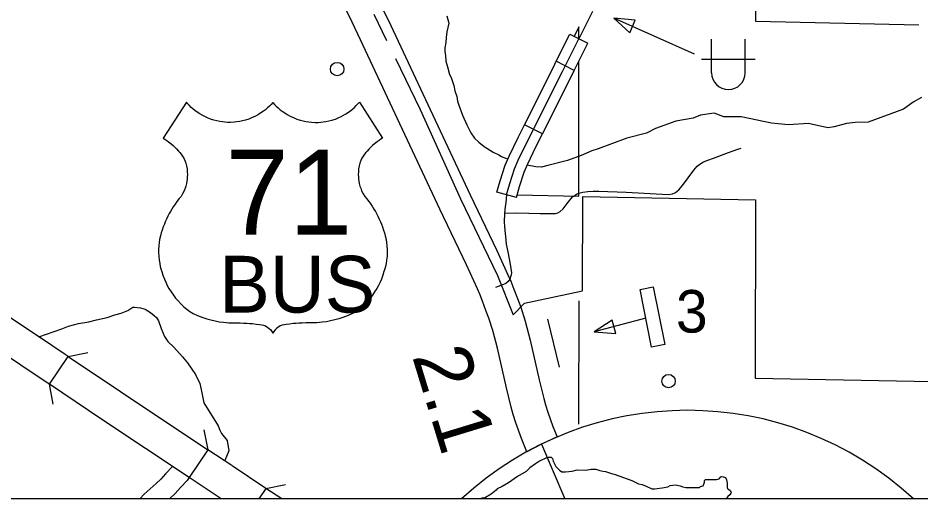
# Model space of a CAD drawing. Extents: x 1382482 to 1385815, y 1168351 to 1170484.
# Drawn here: x 1384529.1 to 1384797.7, y 1168702.4 to 1168845.5 of the extents above; entities that cross this region are included whole.
import ezdxf

# ---------------------------------------------------------------- set-up
doc = ezdxf.new("R2010")
doc.units = 0
for name, color, linetype in [('15', 7, 'Continuous'), ('22', 7, 'Continuous'), ('32', 7, 'Continuous'), ('35', 7, 'Continuous'), ('37', 7, 'Continuous'), ('46', 7, 'Continuous'), ('48', 7, 'Continuous'), ('5', 7, 'Continuous'), ('57', 7, 'Continuous'), ('6', 7, 'Continuous'), ('Default', 7, 'Continuous'), ('R_No Plot', 7, 'Continuous')]:
    doc.layers.add(name, color=color, linetype=linetype)

msp = doc.modelspace()

# ---------------------------------------------------------------- linework, layer by layer
at = {"layer": '15'}
msp.add_line((1384602.84, 1168705.52), (1384592.76, 1168712.26), dxfattribs=at)
for points in [[(1384689.48, 1168720.81), (1384684.86, 1168718.69), (1384680.47, 1168716.41), (1384678.87, 1168720.37), (1384677.21, 1168725.04), (1384676.41, 1168727.54), (1384675.81, 1168729.71), (1384674.38, 1168735.47), (1384671.72, 1168747.23), (1384670.33, 1168752.47), (1384669.17, 1168756.22), (1384668.32, 1168758.5), (1384667.27, 1168761.27), (1384666.5, 1168763.34), (1384665.77, 1168764.88), (1384662.49, 1168772.09), (1384654.58, 1168788.57), (1384641.95, 1168815.49), (1384630.97, 1168839), (1384628.47, 1168844.22), (1384622.3, 1168856.93)], [(1384637.48, 1168848.56), (1384640.01, 1168843.27), (1384651.01, 1168819.73), (1384663.61, 1168792.85), (1384671.55, 1168776.33), (1384674.84, 1168769.09), (1384675.73, 1168767.22), (1384676.63, 1168764.78), (1384677.67, 1168762.03), (1384678.64, 1168759.45), (1384679.94, 1168755.23), (1384681.43, 1168749.62), (1384684.11, 1168737.78), (1384685.48, 1168732.26), (1384686, 1168730.41), (1384686.69, 1168728.23), (1384688.22, 1168723.92), (1384689.48, 1168720.81)], [(1384535.46, 1168750.55), (1384528.18, 1168755.37), (1384526.88, 1168756.23)], [(1384544.01, 1168744.78), (1384542.81, 1168745.59), (1384535.49, 1168750.52)], [(1384529.93, 1168742.21), (1384522.3, 1168747.27), (1384521.35, 1168747.9)], [(1384585.54, 1168717.02), (1384579.98, 1168708.71), (1384553.99, 1168725.99), (1384538.42, 1168736.49), (1384544.01, 1168744.78)], [(1384544.01, 1168744.78), (1384559.55, 1168734.3), (1384585.54, 1168717.02)], [(1384538.42, 1168736.49), (1384537.47, 1168737.13), (1384529.9, 1168742.23)], [(1384684.86, 1168718.69), (1384691.81, 1168702.36)], [(1384592.72, 1168712.29), (1384585.54, 1168717.02)], [(1384589.57, 1168702.36), (1384587.2, 1168703.95), (1384579.98, 1168708.71)], [(1384607.54, 1168702.36), (1384602.84, 1168705.52), (1384600.73, 1168702.36)]]:
    msp.add_lwpolyline(points, dxfattribs=at)
at = {"layer": '22'}
for points in [[(1384604.91, 1168820.38), (1384604.39, 1168819.79), (1384603.89, 1168819.27), (1384603.31, 1168818.74), (1384602.7, 1168818.21), (1384602.1, 1168817.74), (1384601.38, 1168817.24), (1384600.6, 1168816.75), (1384599.72, 1168816.27), (1384598.6, 1168815.75), (1384597.74, 1168815.42), (1384596.77, 1168815.1), (1384595.88, 1168814.87), (1384595.06, 1168814.7), (1384594.2, 1168814.57), (1384593.4, 1168814.49), (1384592.31, 1168814.44), (1384591.43, 1168814.45), (1384590.66, 1168814.49), (1384589.92, 1168814.57), (1384589.18, 1168814.68), (1384588.25, 1168814.87), (1384587.38, 1168815.1), (1384586.33, 1168815.44), (1384585.44, 1168815.79), (1384584.63, 1168816.16), (1384583.89, 1168816.55), (1384583.2, 1168816.95), (1384582.44, 1168817.46), (1384581.74, 1168817.97), (1384581.13, 1168818.47), (1384580.62, 1168818.92), (1384580.1, 1168819.42), (1384579.59, 1168819.96), (1384579.18, 1168820.44), (1384572.25, 1168809.73), (1384572.75, 1168809.43), (1384573.34, 1168809.05), (1384573.89, 1168808.65), (1384574.64, 1168808.07), (1384575.23, 1168807.56), (1384575.76, 1168807.07), (1384576.29, 1168806.52), (1384576.84, 1168805.91), (1384577.24, 1168805.44), (1384577.63, 1168804.94), (1384578.02, 1168804.39), (1384578.4, 1168803.81), (1384578.76, 1168803.13), (1384579.03, 1168802.29), (1384579.23, 1168801.47), (1384579.38, 1168800.58), (1384579.47, 1168799.76), (1384579.49, 1168798.97), (1384579.47, 1168798.23), (1384579.43, 1168797.63), (1384579.33, 1168796.9), (1384579.19, 1168796.22), (1384579, 1168795.47), (1384578.79, 1168794.82), (1384578.51, 1168794.09), (1384578.06, 1168793.15), (1384577.59, 1168792.41), (1384577.04, 1168791.74), (1384576.36, 1168790.87), (1384575.81, 1168790.11), (1384575.3, 1168789.34), (1384574.83, 1168788.59), (1384574.43, 1168787.92), (1384574.08, 1168787.3), (1384573.69, 1168786.55), (1384573.27, 1168785.67), (1384572.9, 1168784.82), (1384572.64, 1168784.18), (1384572.33, 1168783.37), (1384571.99, 1168782.37), (1384571.73, 1168781.54), (1384571.48, 1168780.64), (1384571.24, 1168779.59), (1384571.09, 1168778.65), (1384570.98, 1168777.68), (1384570.91, 1168776.61), (1384570.91, 1168775.61), (1384570.95, 1168774.63), (1384571.07, 1168773.48), (1384571.25, 1168772.4), (1384571.43, 1168771.57), (1384571.62, 1168770.85), (1384571.86, 1168770.03), (1384572.17, 1168769.01), (1384572.63, 1168767.78), (1384573.03, 1168766.87), (1384573.48, 1168765.94), (1384573.98, 1168765.02), (1384574.64, 1168763.97), (1384575.31, 1168763.01), (1384575.96, 1168762.17), (1384576.7, 1168761.3), (1384577.66, 1168760.31), (1384578.47, 1168759.56), (1384579.31, 1168758.86)], [(1384604.91, 1168820.38), (1384605.44, 1168819.79), (1384605.94, 1168819.27), (1384606.51, 1168818.74), (1384607.13, 1168818.21), (1384607.73, 1168817.74), (1384608.45, 1168817.24), (1384609.22, 1168816.75), (1384610.11, 1168816.27), (1384611.23, 1168815.75), (1384612.09, 1168815.42), (1384613.06, 1168815.1), (1384613.95, 1168814.87), (1384614.77, 1168814.7), (1384615.63, 1168814.57), (1384616.43, 1168814.49), (1384617.52, 1168814.44), (1384618.4, 1168814.45), (1384619.17, 1168814.49), (1384619.9, 1168814.57), (1384620.64, 1168814.68), (1384621.58, 1168814.87), (1384622.44, 1168815.1), (1384623.5, 1168815.44), (1384624.39, 1168815.79), (1384625.2, 1168816.16), (1384625.94, 1168816.55), (1384626.62, 1168816.95), (1384627.39, 1168817.46), (1384628.09, 1168817.97), (1384628.7, 1168818.47), (1384629.21, 1168818.92), (1384629.73, 1168819.42), (1384630.24, 1168819.96), (1384630.65, 1168820.44), (1384637.57, 1168809.73), (1384637.08, 1168809.43), (1384636.49, 1168809.05), (1384635.93, 1168808.65), (1384635.19, 1168808.07), (1384634.6, 1168807.56), (1384634.07, 1168807.07), (1384633.53, 1168806.52), (1384632.98, 1168805.91), (1384632.59, 1168805.44), (1384632.2, 1168804.94), (1384631.81, 1168804.39), (1384631.42, 1168803.81), (1384631.07, 1168803.13), (1384630.8, 1168802.29), (1384630.6, 1168801.47), (1384630.44, 1168800.58), (1384630.36, 1168799.76), (1384630.33, 1168798.97), (1384630.35, 1168798.23), (1384630.4, 1168797.63), (1384630.5, 1168796.9), (1384630.63, 1168796.22), (1384630.83, 1168795.47), (1384631.04, 1168794.82), (1384631.32, 1168794.09), (1384631.77, 1168793.15), (1384632.23, 1168792.41), (1384632.79, 1168791.74), (1384633.47, 1168790.87), (1384634.02, 1168790.11), (1384634.53, 1168789.34), (1384635, 1168788.59), (1384635.4, 1168787.92), (1384635.75, 1168787.3), (1384636.14, 1168786.55), (1384636.55, 1168785.67), (1384636.93, 1168784.82), (1384637.19, 1168784.18), (1384637.5, 1168783.37), (1384637.83, 1168782.37), (1384638.1, 1168781.54), (1384638.35, 1168780.64), (1384638.58, 1168779.59), (1384638.74, 1168778.65), (1384638.85, 1168777.68), (1384638.91, 1168776.61), (1384638.92, 1168775.61), (1384638.87, 1168774.63), (1384638.75, 1168773.48), (1384638.58, 1168772.4), (1384638.4, 1168771.57), (1384638.21, 1168770.85), (1384637.97, 1168770.03), (1384637.65, 1168769.01), (1384637.2, 1168767.78), (1384636.8, 1168766.87), (1384636.35, 1168765.94), (1384635.84, 1168765.02), (1384635.19, 1168763.97), (1384634.52, 1168763.01), (1384633.87, 1168762.17), (1384633.13, 1168761.3), (1384632.17, 1168760.31), (1384631.36, 1168759.56), (1384630.52, 1168758.86)], [(1384579.31, 1168758.86), (1384580.18, 1168758.2), (1384581.22, 1168757.52), (1384582.53, 1168756.93), (1384584.06, 1168756.35), (1384585.31, 1168755.94), (1384586.44, 1168755.63), (1384587.71, 1168755.33), (1384588.91, 1168755.11), (1384590.19, 1168754.94), (1384591.81, 1168754.8), (1384593.05, 1168754.75), (1384594.11, 1168754.76), (1384595.14, 1168754.75), (1384596.17, 1168754.72), (1384597.15, 1168754.67), (1384598, 1168754.61), (1384598.84, 1168754.54), (1384599.92, 1168754.43), (1384600.97, 1168754.3), (1384601.6, 1168754.21), (1384602.12, 1168754.11), (1384602.75, 1168753.84), (1384603.11, 1168753.64), (1384603.43, 1168753.44), (1384603.86, 1168753.09), (1384604.27, 1168752.67), (1384604.61, 1168752.24), (1384604.91, 1168751.74)], [(1384630.52, 1168758.86), (1384629.65, 1168758.2), (1384628.61, 1168757.52), (1384627.3, 1168756.93), (1384625.77, 1168756.35), (1384624.51, 1168755.94), (1384623.39, 1168755.63), (1384622.11, 1168755.33), (1384620.92, 1168755.11), (1384619.63, 1168754.94), (1384618.02, 1168754.8), (1384616.78, 1168754.75), (1384615.72, 1168754.76), (1384614.69, 1168754.75), (1384613.66, 1168754.72), (1384612.68, 1168754.67), (1384611.82, 1168754.61), (1384610.98, 1168754.54), (1384609.91, 1168754.43), (1384608.86, 1168754.3), (1384608.23, 1168754.21), (1384607.71, 1168754.11), (1384607.08, 1168753.84), (1384606.71, 1168753.64), (1384606.4, 1168753.44), (1384605.97, 1168753.09), (1384605.56, 1168752.67), (1384605.22, 1168752.24), (1384604.91, 1168751.74)]]:
    msp.add_lwpolyline(points, dxfattribs=at)
at = {"layer": '32'}
for p, q in [((1384694.58, 1168829.93), (1384689.23, 1168832.63)), ((1384685.13, 1168811.06), (1384679.77, 1168813.74)), ((1384677.35, 1168792.1), (1384671.57, 1168793.72))]:
    msp.add_line(p, q, dxfattribs=at)
for points in [[(1384674.46, 1168792.91), (1384675.39, 1168796.21), (1384676.84, 1168800.64), (1384677.93, 1168803.19), (1384680.58, 1168808.66), (1384691.05, 1168829.58), (1384695.95, 1168839.32)], [(1384689.23, 1168832.63), (1384693.27, 1168840.67), (1384698.63, 1168837.97)], [(1384694.58, 1168829.93), (1384698.63, 1168837.97)], [(1384679.77, 1168813.74), (1384688.37, 1168830.92), (1384689.23, 1168832.63)], [(1384685.13, 1168811.06), (1384693.73, 1168828.23), (1384694.58, 1168829.93)], [(1384671.57, 1168793.72), (1384672.52, 1168797.08), (1384674.03, 1168801.71), (1384675.2, 1168804.43), (1384677.89, 1168809.99), (1384679.77, 1168813.74)], [(1384677.35, 1168792.1), (1384678.26, 1168795.34), (1384679.64, 1168799.58), (1384680.66, 1168801.94), (1384683.27, 1168807.34), (1384685.13, 1168811.06)]]:
    msp.add_lwpolyline(points, dxfattribs=at)
at = {"layer": '35'}
for points in [[(1384656.69, 1168846.16), (1384657.27, 1168843.99), (1384656.69, 1168841.37), (1384656.46, 1168839.75), (1384656.42, 1168838.25), (1384656.11, 1168836.63), (1384656.11, 1168835.47), (1384656.23, 1168834.36), (1384656.38, 1168832.66), (1384656.84, 1168830.93), (1384657.42, 1168828.73), (1384657.96, 1168827.81), (1384658.73, 1168825.46), (1384659.07, 1168823.84), (1384659.61, 1168822.15), (1384659.84, 1168820.73), (1384660.27, 1168819.57), (1384661.35, 1168816.6), (1384662.62, 1168813.71), (1384663.85, 1168811.36), (1384664.89, 1168809.74), (1384666.2, 1168808.55), (1384667.74, 1168807.31), (1384670.47, 1168805.58), (1384672.09, 1168804.81), (1384672.89, 1168804.31), (1384674.13, 1168803.81), (1384674.78, 1168803.58)], [(1384797.88, 1168821.89), (1384795.37, 1168820.47), (1384792.48, 1168818.33), (1384782.06, 1168814.46), (1384778.11, 1168814.43), (1384775.52, 1168814.14), (1384771.86, 1168813.07), (1384769.99, 1168812.86), (1384764.28, 1168814.1), (1384758.26, 1168813.7), (1384753.28, 1168814.18), (1384744.22, 1168816.12), (1384739.08, 1168816.12), (1384736.16, 1168817.22), (1384732.18, 1168816.63), (1384729.91, 1168815.74), (1384724.77, 1168814.78), (1384718.77, 1168812.58), (1384716.07, 1168811.24), (1384710.18, 1168809.72), (1384701.71, 1168806.54), (1384699.8, 1168805.93), (1384696.66, 1168804.55), (1384692.56, 1168803.08), (1384686.71, 1168801.56), (1384684.84, 1168801.14), (1384683.12, 1168801.17), (1384680.55, 1168801.72)], [(1384535.28, 1168750.66), (1384542.14, 1168753.01), (1384544.1, 1168753.81), (1384547.13, 1168754.59), (1384550.17, 1168755.07), (1384552.42, 1168755.69), (1384555.61, 1168756.32), (1384557.87, 1168757.21), (1384559.75, 1168757.69), (1384561.8, 1168758.47), (1384563.26, 1168759.41), (1384563.73, 1168759.47), (1384564.68, 1168759.36), (1384565.57, 1168759.21), (1384566.88, 1168758.84), (1384568.5, 1168757.9), (1384569.65, 1168757), (1384570.28, 1168756.32), (1384570.91, 1168755.33), (1384571.69, 1168753.07), (1384572.63, 1168750.72), (1384573.68, 1168749.2), (1384575.46, 1168747.52), (1384578.08, 1168744.64), (1384579.55, 1168742.91), (1384581.9, 1168739.4), (1384583.16, 1168736.72), (1384583.74, 1168733.95), (1384584.42, 1168731.01), (1384588.67, 1168724.13), (1384589.09, 1168722.83), (1384589.67, 1168721.83), (1384591.31, 1168719.81), (1384591.86, 1168716.73), (1384590.67, 1168713.83)], [(1384686.32, 1168714.57), (1384684.25, 1168713.58), (1384683.06, 1168712.85), (1384681.4, 1168711.62), (1384680.32, 1168710.58), (1384677.7, 1168709.07), (1384675.05, 1168707.15), (1384673.12, 1168706.11), (1384671.66, 1168705.42), (1384671.35, 1168704.95), (1384669.89, 1168703.76), (1384668.16, 1168702.84), (1384667.43, 1168702.57), (1384667.08, 1168702.57), (1384666.7, 1168702.36)], [(1384686.32, 1168714.57), (1384686.94, 1168714.8), (1384687.75, 1168714.8), (1384688.13, 1168714.41), (1384688.28, 1168713.6), (1384689.05, 1168712.06), (1384690.21, 1168710.98), (1384690.9, 1168710.48), (1384692.02, 1168710.41), (1384693.98, 1168710.64), (1384695.47, 1168711.02), (1384697.98, 1168710.94), (1384699.64, 1168711.22), (1384701.03, 1168711.18), (1384702.14, 1168710.83), (1384703.03, 1168710.64), (1384703.9, 1168710.58), (1384705.64, 1168709.97), (1384706.49, 1168709.7), (1384711.75, 1168707.81), (1384713.73, 1168706.88), (1384714.8, 1168706.65), (1384715.95, 1168706.14)], [(1384715.95, 1168706.14), (1384717.65, 1168705.4), (1384718.45, 1168705.36), (1384720.73, 1168705.67), (1384722.46, 1168705.94), (1384723.15, 1168706.4), (1384724.65, 1168706.59), (1384726.04, 1168706.29), (1384726.85, 1168705.94), (1384727.77, 1168705.75), (1384728.58, 1168705.79), (1384729.73, 1168705.82), (1384730.5, 1168705.79), (1384731.16, 1168705.79), (1384731.81, 1168705.82), (1384732.12, 1168706.06), (1384732.47, 1168706.13), (1384732.89, 1168706.29), (1384733.16, 1168706.75), (1384733.28, 1168707.37), (1384733.31, 1168707.9), (1384733.66, 1168708.14), (1384733.93, 1168708.17), (1384734.51, 1168708.17), (1384735.16, 1168708.14), (1384735.97, 1168708.14), (1384736.93, 1168708.14), (1384737.66, 1168708.33), (1384738.17, 1168708.91), (1384738.4, 1168709.02), (1384738.97, 1168708.98), (1384739.55, 1168708.71), (1384739.86, 1168708.1), (1384740.05, 1168707.1), (1384740.05, 1168706.56), (1384740.05, 1168706.17), (1384740.09, 1168705.71), (1384740.21, 1168705.52), (1384740.48, 1168705.25), (1384741.01, 1168704.82), (1384741.25, 1168704.4), (1384741.17, 1168704.09), (1384740.9, 1168703.55), (1384740.24, 1168703.13), (1384739.94, 1168702.71), (1384739.8, 1168702.36)], [(1384588.98, 1168702.76), (1384588.84, 1168702.36)]]:
    msp.add_lwpolyline(points, dxfattribs=at)
at = {"layer": '37'}
for points in [[(1384544.01, 1168744.78), (1384549.89, 1168745.93)], [(1384539.56, 1168730.6), (1384538.42, 1168736.49)], [(1384584.33, 1168722.91), (1384585.52, 1168717.03)], [(1384602.84, 1168705.52), (1384608.72, 1168706.69)]]:
    msp.add_lwpolyline(points, dxfattribs=at)
at = {"layer": '46'}
for points in [[(1384575.03, 1168712), (1384573.02, 1168709.8), (1384571.61, 1168708.27), (1384570.21, 1168706.97), (1384568.41, 1168705.35), (1384566.59, 1168703.74), (1384565.31, 1168702.36)], [(1384579.98, 1168708.71), (1384579.41, 1168707.9), (1384577.44, 1168705.74), (1384575.86, 1168704.03), (1384574.26, 1168702.54), (1384574.06, 1168702.36)]]:
    msp.add_lwpolyline(points, dxfattribs=at)
at = {"layer": '5'}
msp.add_lwpolyline([(1384695.9, 1168761.3), (1384695.88, 1168724.63)], dxfattribs=at)
at = {"layer": '57'}
for p, q in [((1384735.44, 1168829.21), (1384735.44, 1168839.21)), ((1384745.44, 1168829.21), (1384745.44, 1168839.21)), ((1384732.44, 1168833.21), (1384748.44, 1168833.21))]:
    msp.add_line(p, q, dxfattribs=at)
msp.add_lwpolyline([(1384730.34, 1168834.78), (1384706.31, 1168845.49)], dxfattribs=at)
msp.add_lwpolyline([(1384711.07, 1168841.13), (1384712.73, 1168844.86), (1384706.31, 1168845.49)], close=True, dxfattribs=at)
msp.add_arc((1384740.44, 1168829.21), 5, 180, 0, dxfattribs=at)
at = {"layer": '6'}
for points in [[(1384797.11, 1168843.4), (1384748.59, 1168844.42), (1384748.71, 1168857.85), (1384740.36, 1168858.07), (1384740.43, 1168866.39), (1384748.78, 1168866.2), (1384748.71, 1168857.85), (1384797.2, 1168856.6)], [(1384634.93, 1168846.64), (1384638.74, 1168838.82)], [(1384695.95, 1168839.32), (1384695.96, 1168842.84), (1384694.54, 1168840.03)], [(1384641.36, 1168833.44), (1384648.72, 1168818.32), (1384660.74, 1168791.71), (1384671.75, 1168768.87), (1384676.42, 1168757.19), (1384679.74, 1168760.63), (1384697.07, 1168764.33), (1384697.09, 1168792.43), (1384748.51, 1168791.38), (1384748.43, 1168738.33), (1384800.97, 1168737.3), (1384801.09, 1168790.31), (1384801.21, 1168840.6)], [(1384677.56, 1168792.86), (1384695.92, 1168792.45), (1384695.95, 1168832.64)]]:
    msp.add_lwpolyline(points, dxfattribs=at)
at = {"layer": 'Default'}
for points in [[(1384700.05, 1168847.45), (1384695.95, 1168839.32)], [(1384695.92, 1168793.34), (1384697.11, 1168793.64), (1384698.57, 1168793.9), (1384700.23, 1168793.99), (1384701.88, 1168793.95), (1384710.03, 1168793.64), (1384722.5, 1168792.99), (1384723.81, 1168793.14), (1384724.73, 1168793.6), (1384725.69, 1168794.41), (1384726.81, 1168795.68), (1384730.14, 1168800.25), (1384731.18, 1168801.4), (1384731.95, 1168802.02), (1384732.99, 1168802.71), (1384734.3, 1168803.21), (1384736.03, 1168803.79), (1384740.42, 1168805.48), (1384743.27, 1168806.45), (1384744.23, 1168806.76)], [(1384674.46, 1168792.91), (1384674.19, 1168790.64), (1384674.05, 1168789.28), (1384673.87, 1168787.4), (1384673.77, 1168784.75), (1384673.81, 1168783.55), (1384673.92, 1168782.27), (1384674.12, 1168780.46), (1384674.35, 1168778.18), (1384674.81, 1168775.87), (1384675.54, 1168772.22), (1384675.89, 1168769.64), (1384675.85, 1168769.02), (1384675.72, 1168768.78), (1384675.38, 1168767.78), (1384674.91, 1168767.08), (1384674.22, 1168766.51), (1384673.53, 1168766.2), (1384671.11, 1168765.28)], [(1384673.87, 1168787.4), (1384676.98, 1168787.48), (1384681.06, 1168787.4), (1384684.44, 1168787.29), (1384687.79, 1168787.29), (1384688.95, 1168787.37), (1384689.72, 1168787.52), (1384690.41, 1168787.9), (1384691.26, 1168788.68), (1384692.49, 1168790.29), (1384694.07, 1168792.26), (1384694.46, 1168792.48)], [(1384694.46, 1168792.48), (1384694.99, 1168792.9), (1384695.49, 1168793.21), (1384695.92, 1168793.34)], [(1384686.65, 1168755.92), (1384690.08, 1168741.61)], [(1384715.87, 1168756.14), (1384700.47, 1168752.06)]]:
    msp.add_lwpolyline(points, dxfattribs=at)
for points in [[(1384714.14, 1168764.72), (1384718.06, 1168765.5), (1384721.52, 1168748.35), (1384717.6, 1168747.56)], [(1384706.91, 1168751.65), (1384705.87, 1168755.6), (1384700.47, 1168752.06)]]:
    msp.add_lwpolyline(points, close=True, dxfattribs=at)
for centre in [(1384624.05, 1168830.31), (1384722.63, 1168737.44)]:
    msp.add_circle(centre, 2, dxfattribs=at)
msp.add_arc((1384728.27, 1168629.93), 98.81, 47.145, 132.855, dxfattribs=at)
at = {"layer": 'R_No Plot'}
msp.add_lwpolyline([(1383432.46, 1169579.7), (1384939.88, 1169579.7), (1384939.88, 1168702.36), (1383432.46, 1168702.36)], close=True, dxfattribs=at)

# ---------------------------------------------------------------- texts
at = {"layer": '22'}
for s, height, p in [('71', 25.344, (1384590.83, 1168781)), ('BUS', 16.896, (1384588.95, 1168757.83))]:
    msp.add_text(s, height=height, dxfattribs=at).set_placement(p)
at = {"layer": '48'}
msp.add_text('2.1', height=16.896, rotation=286.9919, dxfattribs=at).set_placement((1384646.27, 1168744.91))
at = {"layer": 'Default'}
msp.add_text('3', height=12.67, dxfattribs=at).set_placement((1384724.83, 1168751.88))

doc.saveas('drawing.dxf')
